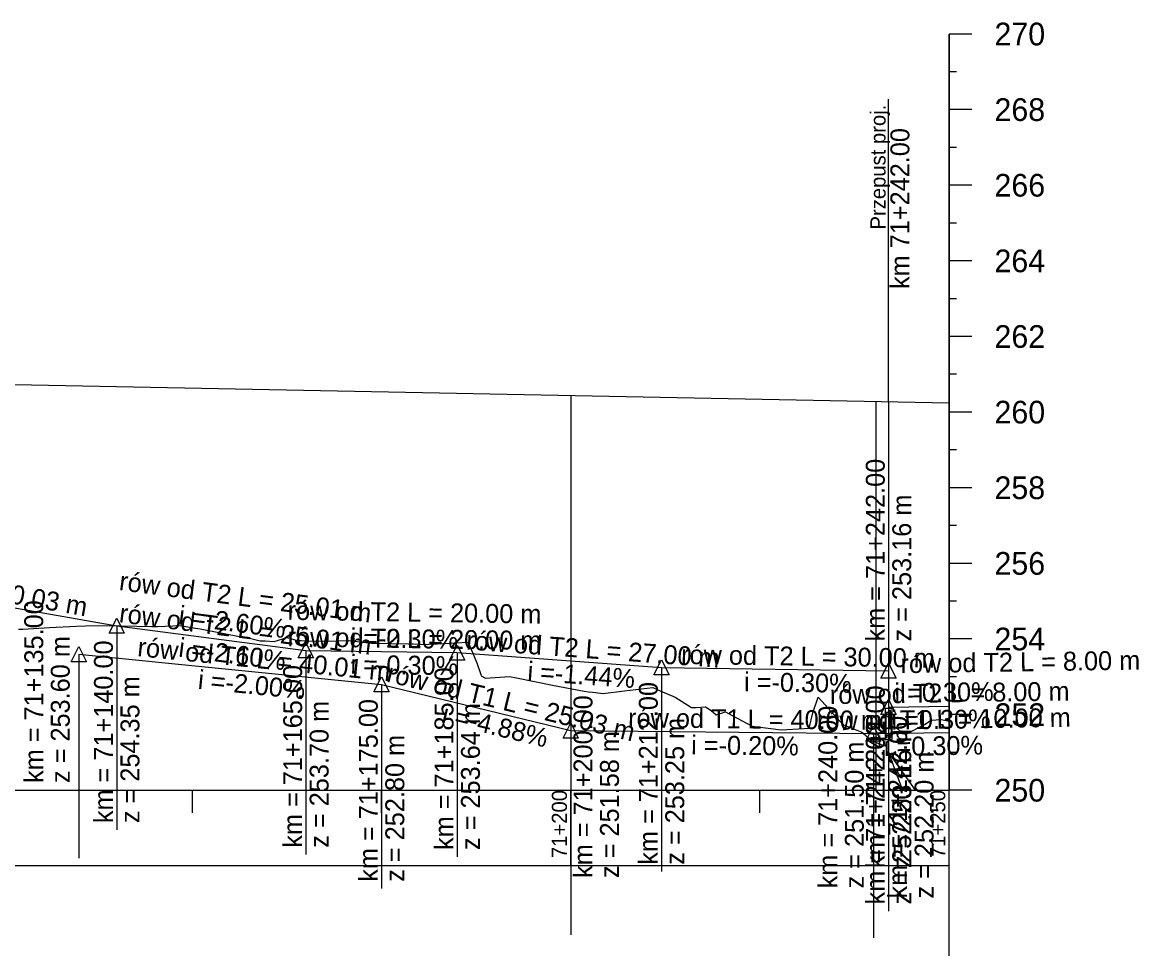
# Model space of a CAD drawing. Extents: x 6531046 to 6533341, y 5514966 to 5518007.
# Drawn here: x 6532973.5 to 6533121.1, y 5516569.5 to 5516692 of the extents above; entities that cross this region are included whole.
import ezdxf

# ---------------------------------------------------------------- set-up
doc = ezdxf.new("R2010")
doc.units = 0
for name, color, linetype in [('IR_default', 7, 'Continuous'), ('TOR_PROF-obiekty+opisy', 7, 'Continuous'), ('TOR_PROF-opisy pomocnicze', 7, 'Continuous'), ('TOR_PROF-rowy otwarte', 7, 'Continuous'), ('TOR_PROF-rozjazdy', 7, 'Continuous'), ('TOR_PROF-tabelka-pochylenia proj T1', 7, 'Continuous'), ('TOR_PROF-tabelka-warstwa ochronna T1', 7, 'Continuous'), ('TOR_PROF-tor projektowany', 7, 'Continuous'), ('TOR_PROF-uklad odniesienia', 7, 'Continuous'), ('TOR_PRZEK_P-tory projektowane', 7, 'Continuous')]:
    doc.layers.add(name, color=color, linetype=linetype)

msp = doc.modelspace()

# ---------------------------------------------------------------- linework, layer by layer
at = {"layer": 'IR_default'}
msp.add_lwpolyline([(6532973.05, 5516611.77), (6532973.63, 5516611.75), (6532977.15, 5516611.96), (6532980.71, 5516612.16), (6532981.9, 5516612.2), (6532983.63, 5516612.26), (6532986.64, 5516612.19), (6532990.66, 5516612.1), (6532991.39, 5516612.13), (6532994.46, 5516612.25), (6532996.14, 5516611.95), (6532997.07, 5516611.79), (6533000.89, 5516611.05), (6533003.45, 5516610.55), (6533003.52, 5516610.56), (6533003.56, 5516610.59), (6533004.97, 5516610.23), (6533005.64, 5516610.2), (6533006.84, 5516610.15), (6533008.56, 5516610.66), (6533009.86, 5516610.27), (6533010.38, 5516610.24), (6533011.43, 5516610.18), (6533015.13, 5516610.23), (6533016.69, 5516610.25), (6533019.69, 5516609.9), (6533019.88, 5516609.9), (6533024.63, 5516609.84), (6533025.26, 5516609.84), (6533027.05, 5516609.73), (6533027.5, 5516609.82), (6533028.4, 5516609.82), (6533029.38, 5516609.87), (6533032.47, 5516610.04), (6533033.61, 5516607.29), (6533034.12, 5516605.76), (6533034.19, 5516605.57), (6533034.77, 5516605.3), (6533037.95, 5516605.5), (6533038.87, 5516605.31), (6533043.62, 5516604.37), (6533047.78, 5516603.54), (6533048.37, 5516603.48), (6533048.88, 5516603.44), (6533049.3, 5516603.37), (6533050.26, 5516603.24), (6533053.12, 5516603.59), (6533056.88, 5516604.06), (6533057.86, 5516603.62), (6533059.81, 5516602.76), (6533061.98, 5516601.39), (6533062.61, 5516601.42), (6533063.84, 5516601.47), (6533064.56, 5516601), (6533065.25, 5516600.45), (6533066.48, 5516600.81), (6533067.36, 5516600.34), (6533070.01, 5516598.93), (6533072.11, 5516598.67), (6533073.84, 5516598.45), (6533076.86, 5516598.62), (6533077.51, 5516598.66), (6533078.02, 5516600.71), (6533078.73, 5516602.79), (6533079.63, 5516601.74), (6533081.6, 5516599.61), (6533082.06, 5516599.12), (6533084.48, 5516598.13), (6533084.68, 5516597.99), (6533085.67, 5516597.11), (6533085.94, 5516596.95), (6533086, 5516596.97), (6533086.35, 5516596.8), (6533087.27, 5516596.37), (6533087.57, 5516596.35), (6533088.6, 5516597.9), (6533089.08, 5516598), (6533090.42, 5516597.91), (6533091.11, 5516598.28), (6533092.75, 5516599.15), (6533093.67, 5516599.74), (6533094.96, 5516599.81), (6533095.86, 5516599.66), (6533096.02, 5516599.63)], dxfattribs=at)
at = {"layer": 'TOR_PROF-obiekty+opisy'}
msp.add_line((6533088.02, 5516641.84), (6533088.02, 5516681.84), dxfattribs=at)
for points in [[(6533088.48, 5516601.27), (6533087.56, 5516601.27), (6533087.56, 5516597.19), (6533088.48, 5516597.19)], [(6533088.4, 5516600.73), (6533087.65, 5516600.73), (6533087.65, 5516597.73), (6533088.4, 5516597.73)]]:
    msp.add_lwpolyline(points, close=True, dxfattribs=at)
for points in [[(6533088.48, 5516597.19), (6533088.48, 5516601.27), (6533087.56, 5516601.27), (6533087.56, 5516597.19), (6533088.48, 5516597.19)], [(6533088.4, 5516597.73), (6533087.65, 5516597.73), (6533087.65, 5516600.73), (6533088.4, 5516600.73), (6533088.4, 5516597.73)]]:
    msp.add_lwpolyline(points, dxfattribs=at)
at = {"layer": 'TOR_PROF-opisy pomocnicze'}
for p, q in [((6532986.02, 5516612.21), (6532986.02, 5516585.21)), ((6532981.02, 5516608.46), (6532981.02, 5516581.46)), ((6533011.02, 5516608.96), (6533011.02, 5516581.96)), ((6533031.02, 5516608.66), (6533031.02, 5516581.66)), ((6533058.02, 5516606.71), (6533058.02, 5516579.71)), ((6533088.02, 5516606.26), (6533088.02, 5516579.26)), ((6533021.02, 5516604.46), (6533021.02, 5516577.46)), ((6533088.02, 5516601.46), (6533088.02, 5516574.46)), ((6533046.02, 5516598.36), (6533046.02, 5516571.36)), ((6533086.02, 5516597.96), (6533086.02, 5516570.96))]:
    msp.add_line(p, q, dxfattribs=at)
for points in [[(6532986.02, 5516613.21), (6532987.02, 5516611.21), (6532985.02, 5516611.21)], [(6532981.02, 5516609.46), (6532982.02, 5516607.46), (6532980.02, 5516607.46)], [(6533011.02, 5516609.96), (6533012.02, 5516607.96), (6533010.02, 5516607.96)], [(6533031.02, 5516609.66), (6533032.02, 5516607.66), (6533030.02, 5516607.66)], [(6533058.02, 5516607.71), (6533059.02, 5516605.71), (6533057.02, 5516605.71)], [(6533088.02, 5516607.26), (6533089.02, 5516605.26), (6533087.02, 5516605.26)], [(6533021.02, 5516605.46), (6533022.02, 5516603.46), (6533020.02, 5516603.46)], [(6533088.02, 5516602.46), (6533089.02, 5516600.46), (6533087.02, 5516600.46)], [(6533046.02, 5516599.36), (6533047.02, 5516597.36), (6533045.02, 5516597.36)], [(6533086.02, 5516598.96), (6533087.02, 5516596.96), (6533085.02, 5516596.96)]]:
    msp.add_lwpolyline(points, close=True, dxfattribs=at)
at = {"layer": 'TOR_PROF-rowy otwarte'}
for p, q in [((6532936.02, 5516620.96), (6532986.02, 5516612.21)), ((6532986.02, 5516612.21), (6533011.02, 5516608.96)), ((6532981.02, 5516608.46), (6533021.02, 5516604.46)), ((6533011.02, 5516608.96), (6533031.02, 5516608.66)), ((6533031.02, 5516608.66), (6533058.02, 5516606.71)), ((6533058.02, 5516606.71), (6533088.02, 5516606.26)), ((6533021.02, 5516604.46), (6533046.02, 5516598.36)), ((6533088.02, 5516601.46), (6533096.02, 5516601.58)), ((6533046.02, 5516598.36), (6533086.02, 5516597.96)), ((6533086.02, 5516597.96), (6533096.02, 5516598.11))]:
    msp.add_line(p, q, dxfattribs=at)
for points in [[(6533096.02, 5516690.46), (6533096.02, 5516595.46), (6533096.02, 5516590.46), (6533096.02, 5516590.46)], [(6532986.02, 5516612.21), (6532986.02, 5516595.46), (6532986.02, 5516590.46), (6532986.02, 5516590.46)], [(6532981.02, 5516608.46), (6532981.02, 5516595.46), (6532981.02, 5516590.46), (6532981.02, 5516590.46)], [(6533011.02, 5516608.96), (6533011.02, 5516595.46), (6533011.02, 5516590.46), (6533011.02, 5516590.46)], [(6533031.02, 5516608.66), (6533031.02, 5516595.46), (6533031.02, 5516590.46), (6533031.02, 5516590.46)], [(6533058.02, 5516606.71), (6533058.02, 5516595.46), (6533058.02, 5516590.46), (6533058.02, 5516590.46)], [(6533088.02, 5516606.26), (6533088.02, 5516595.46), (6533088.02, 5516590.46), (6533088.02, 5516590.46)], [(6533021.02, 5516604.46), (6533021.02, 5516595.46), (6533021.02, 5516590.46), (6533021.02, 5516590.46)], [(6533088.02, 5516601.46), (6533088.02, 5516595.46), (6533091.52, 5516590.46), (6533091.52, 5516590.46)], [(6533096.02, 5516601.58), (6533096.02, 5516595.46), (6533096.02, 5516590.46), (6533096.02, 5516590.46)], [(6533046.02, 5516598.36), (6533046.02, 5516595.46), (6533046.02, 5516590.46), (6533046.02, 5516590.46)], [(6533086.02, 5516597.96), (6533086.02, 5516595.46), (6533086.02, 5516590.46), (6533086.02, 5516590.46)], [(6533096.02, 5516598.11), (6533096.02, 5516595.46), (6533096.02, 5516590.46), (6533096.02, 5516590.46)]]:
    msp.add_lwpolyline(points, dxfattribs=at)
at = {"layer": 'TOR_PROF-tabelka-pochylenia proj T1'}
msp.add_lwpolyline([(6531096.02, 5516565.46), (6533096.02, 5516565.46), (6533096.02, 5516580.46), (6531096.02, 5516580.46)], close=True, dxfattribs=at)
at = {"layer": 'TOR_PROF-tabelka-warstwa ochronna T1'}
for points in [[(6533088.02, 5516641.84), (6533088.02, 5516595.46), (6533088.02, 5516590.46), (6533088.02, 5516590.46)], [(6533096.02, 5516641.69), (6533096.02, 5516595.46), (6533096.02, 5516590.46), (6533096.02, 5516590.46)]]:
    msp.add_lwpolyline(points, dxfattribs=at)
at = {"layer": 'TOR_PROF-tor projektowany'}
for p in [(6531846.02, 5516666.11), (6531883.59, 5516665.38)]:
    msp.add_line(p, (6533096.02, 5516641.69), dxfattribs=at)
for points in [[(6533046.02, 5516642.66), (6533046.02, 5516595.46), (6533046.02, 5516590.46), (6533046.02, 5516590.46)], [(6533086.35, 5516641.87), (6533086.35, 5516595.46), (6533086.35, 5516590.46), (6533086.35, 5516590.46)], [(6533088.02, 5516641.84), (6533088.02, 5516595.46), (6533088.02, 5516590.46), (6533088.02, 5516590.46)], [(6533088.02, 5516641.84), (6533088.02, 5516595.46), (6533089.85, 5516590.46), (6533089.85, 5516590.46)], [(6533096.02, 5516641.69), (6533096.02, 5516595.46), (6533096.02, 5516590.46), (6533096.02, 5516590.46)]]:
    msp.add_lwpolyline(points, dxfattribs=at)
at = {"layer": 'TOR_PROF-uklad odniesienia'}
for p, q in [((6533096.02, 5516590.46), (6533096.02, 5516690.46)), ((6533099.02, 5516690.46), (6533096.02, 5516690.46)), ((6533097.02, 5516685.46), (6533096.02, 5516685.46)), ((6533099.02, 5516680.46), (6533096.02, 5516680.46)), ((6533097.02, 5516675.46), (6533096.02, 5516675.46)), ((6533099.02, 5516670.46), (6533096.02, 5516670.46)), ((6533097.02, 5516665.46), (6533096.02, 5516665.46)), ((6533099.02, 5516660.46), (6533096.02, 5516660.46)), ((6533097.02, 5516655.46), (6533096.02, 5516655.46)), ((6533099.02, 5516650.46), (6533096.02, 5516650.46)), ((6533097.02, 5516645.46), (6533096.02, 5516645.46)), ((6533099.02, 5516640.46), (6533096.02, 5516640.46)), ((6533097.02, 5516635.46), (6533096.02, 5516635.46)), ((6533099.02, 5516630.46), (6533096.02, 5516630.46)), ((6533097.02, 5516625.46), (6533096.02, 5516625.46)), ((6533099.02, 5516620.46), (6533096.02, 5516620.46)), ((6533097.02, 5516615.46), (6533096.02, 5516615.46)), ((6533099.02, 5516610.46), (6533096.02, 5516610.46)), ((6533097.02, 5516605.46), (6533096.02, 5516605.46)), ((6533099.02, 5516600.46), (6533096.02, 5516600.46)), ((6533097.02, 5516595.46), (6533096.02, 5516595.46)), ((6531096.02, 5516590.46), (6533096.02, 5516590.46)), ((6532996.02, 5516587.46), (6532996.02, 5516590.46)), ((6533021.02, 5516587.46), (6533021.02, 5516590.46)), ((6533046.02, 5516580.46), (6533046.02, 5516590.46)), ((6533071.02, 5516587.46), (6533071.02, 5516590.46)), ((6533099.02, 5516590.46), (6533096.02, 5516590.46)), ((6533096.02, 5516580.46), (6533096.02, 5516590.46))]:
    msp.add_line(p, q, dxfattribs=at)

# ---------------------------------------------------------------- texts
at = {"layer": 'TOR_PROF-opisy pomocnicze'}
for s, rotation, p in [('km = 71+242.00', 90, (6533087.52, 5516610.13)), ('z = 253.16 m', 90, (6533091.02, 5516610.13)), ('rów od T2 L = 50.03 m', 350.0738, (6532948.86, 5516619.23)), ('rów od T2 L = 25.01 m', 352.5931, (6532986.25, 5516616.94)), ('km = 71+135.00', 90, (6532976.31, 5516591.42)), ('rów od T2 L = 20.00 m', 359.1406, (6533008.59, 5516613)), ('rów od T2 L = 25.01 m', 352.5931, (6532986.25, 5516612.69)), ('  i =-2.60%', 352.5931, (6532992.26, 5516612.63)), ('rów od T2 L = 20.00 m', 359.1406, (6533008.59, 5516609.5)), ('  i =-0.30%', 359.1406, (6533015.05, 5516609.4)), ('rów od T2 L = 27.00 m', 355.8691, (6533032.15, 5516609.08)), ('z = 253.60 m', 90, (6532979.81, 5516591.42)), ('km = 71+140.00', 90, (6532985.52, 5516586.11)), ('rów od T1 L = 40.01 m', 354.2895, (6532988.69, 5516608.2)), ('  i =-2.60%', 352.5931, (6532992.26, 5516608.38)), ('rów od T2 L = 30.00 m', 359.1406, (6533060.59, 5516607.17)), ('  i =-0.30%', 359.1406, (6533015.05, 5516605.9)), ('rów od T2 L = 8.00 m', 0.8594, (6533089.62, 5516605.94)), ('  i =-2.00%', 354.2895, (6532994.83, 5516604.07)), ('km = 71+165.00', 90, (6533010.52, 5516582.86)), ('rów od T1 L = 25.03 m', 346.2877, (6533021.56, 5516604.85)), ('km = 71+185.00', 90, (6533030.52, 5516582.56)), ('  i =-1.44%', 355.8691, (6533038.39, 5516605.12)), ('z = 254.35 m', 90, (6532989.02, 5516586.11)), ('  i =-0.30%', 359.1406, (6533067.05, 5516603.58)), ('km = 71+212.00', 90, (6533057.52, 5516580.61)), ('rów od T2 L = 8.00 m', 0.8594, (6533080.28, 5516601.85)), ('km = 71+242.00', 90, (6533087.52, 5516580.16)), ('  i =0.30%', 0.8594, (6533086.96, 5516602.05)), ('z = 253.70 m', 90, (6533014.02, 5516582.86)), ('km = 71+175.00', 90, (6533020.52, 5516578.36)), ('km = 71+200.00', 90, (6533048.89, 5516578.86)), ('  i =-4.88%', 346.2877, (6533027.05, 5516599.9)), ('z = 253.64 m', 90, (6533034.02, 5516582.56)), ('rów od T1 L = 40.00 m', 359.4271, (6533053.59, 5516598.79)), ('km = 71+240.00', 90, (6533081.25, 5516577.48)), ('rów od T1 L = 10.00 m', 0.8594, (6533078.58, 5516598.35)), ('  i =0.30%', 0.8594, (6533086.56, 5516598.44)), ('z = 253.25 m', 90, (6533061.02, 5516580.61)), ('km = 71+242.00', 90, (6533087.52, 5516575.36)), ('km = 71+242.00', 90, (6533090.47, 5516576.14)), ('z = 253.16 m', 90, (6533091.02, 5516580.16)), ('z = 252.80 m', 90, (6533024.02, 5516578.36)), ('z = 251.58 m', 90, (6533052.39, 5516578.86)), ('  i =-0.20%', 359.4271, (6533060.07, 5516595.22)), ('  i =0.30%', 0.8594, (6533085.56, 5516594.96)), ('z = 251.50 m', 90, (6533084.75, 5516577.48)), ('z = 252.20 m', 90, (6533093.97, 5516576.14)), ('z = 252.20 m', 90, (6533091.02, 5516575.36))]:
    msp.add_text(s, height=2.5, rotation=rotation, dxfattribs=at).set_placement(p)
at = {"layer": 'TOR_PROF-rozjazdy'}
msp.add_text('km 71+242.00', height=2.5, rotation=90, dxfattribs=at).set_placement((6533090.77, 5516656.74))
at = {"layer": 'TOR_PROF-uklad odniesienia'}
for s, p in [('270', (6533102.02, 5516688.96)), ('268', (6533102.02, 5516678.96)), ('266', (6533102.02, 5516668.96)), ('264', (6533102.02, 5516658.96)), ('262', (6533102.02, 5516648.96)), ('260', (6533102.02, 5516638.96)), ('258', (6533102.02, 5516628.96)), ('256', (6533102.02, 5516618.96)), ('254', (6533102.02, 5516608.96)), ('252', (6533102.02, 5516598.96)), ('250', (6533102.02, 5516588.96))]:
    msp.add_text(s, height=3, dxfattribs=at).set_placement(p)
for s, p in [('71+200', (6533045.52, 5516581.49)), ('71+250', (6533095.52, 5516581.49))]:
    msp.add_text(s, height=2, rotation=90, dxfattribs=at).set_placement(p)
at = {"layer": 'TOR_PRZEK_P-tory projektowane'}
msp.add_text('Przepust proj.', height=2, rotation=90, dxfattribs=at).set_placement((6533087.62, 5516664.61))

doc.saveas('drawing.dxf')
